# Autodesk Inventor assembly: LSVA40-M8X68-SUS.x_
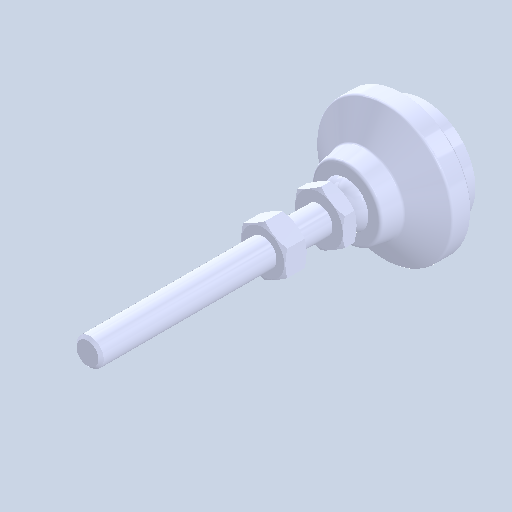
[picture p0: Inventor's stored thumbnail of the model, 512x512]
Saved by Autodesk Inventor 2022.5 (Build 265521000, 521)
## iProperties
Created: 2024-08
Part Number: LSVA40-M8X68-SUS.x_
Document SubType Name: Assembly
Designer: ImaoCorp
Author: ImaoCorp
Sending System: SOLIDWORKS 2022-2022290
MC: AMD64
MC_MODEL: Intel64 Family 6 Model 60 Stepping 3, GenuineIntel
OS: Windows_NT
FRU: Parasolid Version 33.1, build 260,  4-25-2022
FORMAT: text
GUISE: transmit
KEY: FILELSVA40-M8X68-SUS.x_t
DATE: Fri Aug 23 16:08:02 2024
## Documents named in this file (4)
- X:\14_SW2022-Inv2022\06_2024-10新製品(SME)\ELS_データ\l\lsva40-m8x68-sus\LSVA40-M8X68-SUS.x_.iam
- X:\14_SW2022-Inv2022\06_2024-10新製品(SME)\ELS_データ\l\lsva40-m8x68-sus\LSVA40-M8X68-SUS_01.ipt
- X:\14_SW2022-Inv2022\06_2024-10新製品(SME)\ELS_データ\l\lsva40-m8x68-sus\LSVA40-M8X68-SUS_02.ipt
- X:\14_SW2022-Inv2022\06_2024-10新製品(SME)\ELS_データ\l\lsva40-m8x68-sus\LSVA40-M8X68-SUS_03.ipt
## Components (3 placed, 3 different names)
1. LSVA40-M8X68-SUS_01
2. LSVA40-M8X68-SUS_02
3. LSVA40-M8X68-SUS_03
